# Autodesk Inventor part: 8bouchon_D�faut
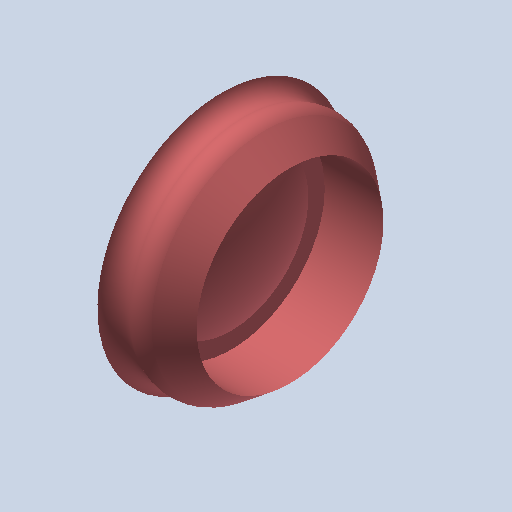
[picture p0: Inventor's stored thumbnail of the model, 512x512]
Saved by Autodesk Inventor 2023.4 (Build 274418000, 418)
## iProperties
Created: 2011-01
Part Number: 8bouchon_D�faut
Document SubType Name: Modeling
Designer: eric
Density: 1 g/cm^3
Mass: 6.01056 g
Surface Area: 52.9548 cm^2
Volume: 6.01056 cm^3
Material: Générique
Appearance: 255,128,128_1
Author: eric
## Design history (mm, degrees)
feature "Base1"
node "Corps solides"
node "Corps surfaciques"
node "Solide1"
